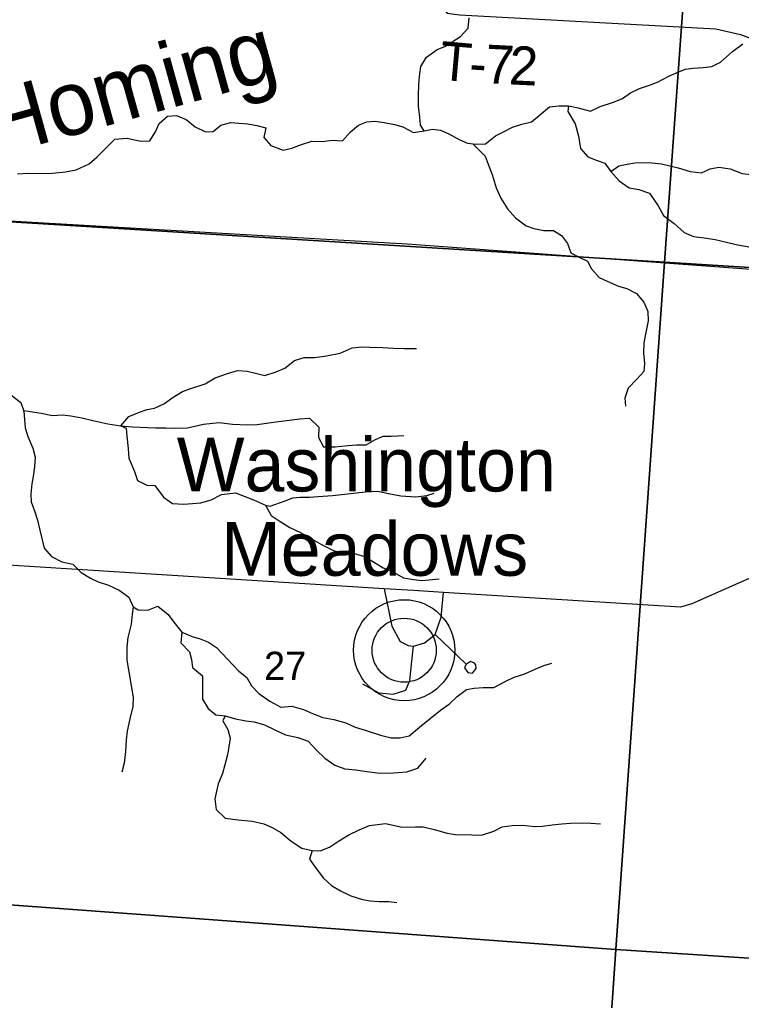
# Model space of a CAD drawing. Extents: x 0 to 42.5, y 0 to 22.
# Drawn here: x 4.014 to 4.545, y 19.377 to 20.099 of the extents above; entities that cross this region are included whole.
import ezdxf

# ---------------------------------------------------------------- set-up
doc = ezdxf.new("R2010")
doc.units = 0
for name, color, linetype in [('GM_X_County_Road', 7, 'Continuous'), ('GM_X_Minor_River', 7, 'Continuous'), ('GM_X_Minor_River_Text', 7, 'Continuous'), ('GM_X_Rail_Line', 7, 'Continuous'), ('GM_X_Section', 7, 'Continuous'), ('GM_X_Section_Text', 7, 'Continuous'), ('GM_X_Township_Road', 7, 'Continuous'), ('GM_X_Township_Road_Text', 7, 'Continuous'), ('GM_X_Unincorporated', 7, 'Continuous'), ('GM_X_Unincorporated_Location', 7, 'Continuous'), ('GM_X_Unincorporated_Text', 7, 'Continuous')]:
    doc.layers.add(name, color=color, linetype=linetype)

msp = doc.modelspace()

# ---------------------------------------------------------------- linework, layer by layer
at = {"layer": 'GM_X_County_Road'}
msp.add_lwpolyline([(4.55979, 19.69172), (4.5089, 19.66909), (4.50055, 19.66669), (4.32613, 19.67757), (4.30419, 19.67894), (4.28243, 19.68029), (3.95904, 19.70046)], dxfattribs=at)
at = {"layer": 'GM_X_Minor_River'}
for points in [[(4.31187, 20.01728), (4.30924, 20.02148), (4.30871, 20.02738), (4.30781, 20.03555), (4.30767, 20.04316), (4.30791, 20.05152), (4.30851, 20.05721), (4.3095, 20.06462), (4.31371, 20.07143), (4.32152, 20.07709), (4.32702, 20.07933), (4.33863, 20.08686), (4.34435, 20.0929), (4.34515, 20.1005)], [(4.15668, 20.01695), (4.1624, 20.02147), (4.1698, 20.02352), (4.17567, 20.02291), (4.18211, 20.02249), (4.18892, 20.0213), (4.19535, 20.01955), (4.19398, 20.01234), (4.19925, 20.00641), (4.20814, 20.00313), (4.21459, 20.0046), (4.22181, 20.00722), (4.22921, 20.00964), (4.23679, 20.00959), (4.24456, 20.01049), (4.25176, 20.01007), (4.25767, 20.01649), (4.26358, 20.02158), (4.26966, 20.02383), (4.27553, 20.02436), (4.28254, 20.02336), (4.29011, 20.02198), (4.29616, 20.02024), (4.30409, 20.01619), (4.31187, 20.01728), (4.31813, 20.01857), (4.324, 20.01778), (4.33005, 20.01508), (4.3376, 20.01085), (4.34384, 20.00834), (4.35008, 20.00754), (4.3571, 20.00768), (4.36433, 20.01353), (4.37079, 20.01691), (4.37687, 20.01991), (4.3839, 20.02214), (4.39092, 20.024), (4.39663, 20.02852), (4.40425, 20.03494), (4.41108, 20.03584), (4.41809, 20.03561), (4.42528, 20.03423), (4.43417, 20.03189), (4.44139, 20.03527), (4.45126, 20.03844), (4.45791, 20.04105), (4.46381, 20.0452), (4.47027, 20.04839), (4.47844, 20.05118), (4.48394, 20.05343), (4.49136, 20.05737), (4.49858, 20.06056), (4.50427, 20.06261), (4.50977, 20.06353), (4.51717, 20.06405), (4.52342, 20.06477), (4.52989, 20.06777), (4.53884, 20.07569), (4.54645, 20.08134)], [(4.41809, 20.03561), (4.41768, 20.03143), (4.42312, 20.02246), (4.42553, 20.01332), (4.42699, 20.00438), (4.43226, 19.99827), (4.43907, 19.99556), (4.44474, 19.99363), (4.44925, 19.98733), (4.45546, 19.98044), (4.46282, 19.97546), (4.46982, 19.97408), (4.47776, 19.97156), (4.48415, 19.96202), (4.48808, 19.95496), (4.49582, 19.94921), (4.50317, 19.94251), (4.51016, 19.93961), (4.51792, 19.93861), (4.52587, 19.93742), (4.53439, 19.93528), (4.54139, 19.93371), (4.55066, 19.93194)], [(4.01287, 19.98556), (4.02083, 19.98608), (4.0358, 19.98599), (4.04812, 19.98724), (4.0559, 19.98852), (4.0654, 19.99302), (4.0715, 19.99811), (4.07722, 20.00416), (4.08446, 20.01114), (4.09337, 20.01203), (4.10321, 20.00969), (4.11003, 20.00984), (4.11443, 20.01665), (4.11712, 20.02271), (4.12303, 20.028), (4.12985, 20.02852), (4.13684, 20.02563), (4.14344, 20.02026), (4.15119, 20.0166), (4.15668, 20.01695)], [(4.34764, 20.00785), (4.35685, 19.99875), (4.35965, 19.99094), (4.36189, 19.98523), (4.36486, 19.97532), (4.36822, 19.9677), (4.37329, 19.95988), (4.37912, 19.95319), (4.38705, 19.94744), (4.39272, 19.9455), (4.39991, 19.94393), (4.40711, 19.94408), (4.41296, 19.94024), (4.41728, 19.93432), (4.41989, 19.92746), (4.42632, 19.924), (4.43198, 19.92149), (4.43498, 19.91577), (4.44063, 19.90927), (4.44648, 19.90657), (4.45499, 19.9031), (4.46104, 19.90116), (4.46803, 19.89769), (4.47348, 19.8912), (4.47648, 19.88434), (4.47681, 19.87749), (4.47487, 19.86895), (4.47349, 19.86136), (4.47326, 19.85376), (4.47397, 19.84615), (4.47355, 19.84027), (4.4684, 19.8346), (4.46192, 19.8278), (4.4596, 19.82059), (4.45995, 19.8147)], [(4.44925, 19.98733), (4.45515, 19.99166), (4.46122, 19.99276), (4.46691, 19.99367), (4.47259, 19.99402), (4.47941, 19.99378), (4.48642, 19.99298), (4.49872, 19.99005), (4.50761, 19.98733), (4.51594, 19.98633), (4.5224, 19.98933), (4.52866, 19.99062), (4.53699, 19.98923), (4.54587, 19.98595), (4.55742, 19.98473), (4.56387, 19.98583), (4.57071, 19.98902), (4.58059, 19.99295), (4.59687, 20.00566)], [(4.08886, 19.80016), (4.09478, 19.80697), (4.10257, 19.81034), (4.10807, 19.8122), (4.11357, 19.81312), (4.12098, 19.81668), (4.1265, 19.82083), (4.13411, 19.82553), (4.14038, 19.82758), (4.15082, 19.83112), (4.15823, 19.83545), (4.16716, 19.83862), (4.17475, 19.84085), (4.18176, 19.84043), (4.18782, 19.83906), (4.19463, 19.8373), (4.20222, 19.83973), (4.20944, 19.84253), (4.21667, 19.84837), (4.2237, 19.85042), (4.23128, 19.85056), (4.24019, 19.85165), (4.25005, 19.85367), (4.25898, 19.85761), (4.26619, 19.85832), (4.27206, 19.85809), (4.28153, 19.85784), (4.2893, 19.85741), (4.29725, 19.85717), (4.30635, 19.85711)], [(4.0079, 19.82311), (4.01526, 19.81736), (4.0175, 19.81107), (4.01802, 19.80461), (4.01837, 19.79872), (4.02041, 19.79243), (4.02396, 19.78386), (4.02581, 19.777), (4.0252, 19.76998), (4.02421, 19.76295), (4.02323, 19.75744), (4.02262, 19.75004), (4.02277, 19.74433), (4.02557, 19.73691), (4.02743, 19.73062), (4.02928, 19.72339), (4.03094, 19.71635), (4.03242, 19.71025), (4.03788, 19.70395), (4.04543, 19.7001), (4.05357, 19.69834), (4.05959, 19.69222), (4.06658, 19.68799), (4.07225, 19.68529), (4.07981, 19.68296), (4.08756, 19.67911), (4.09473, 19.67413), (4.09791, 19.66707), (4.09712, 19.66157), (4.09631, 19.65416), (4.09398, 19.64448), (4.09318, 19.63727), (4.09331, 19.62776), (4.0944, 19.62054), (4.09531, 19.61483), (4.0966, 19.60741), (4.09788, 19.60056), (4.09765, 19.59353), (4.09532, 19.58461), (4.09356, 19.5755), (4.09276, 19.56904), (4.09233, 19.5605), (4.09133, 19.55176), (4.08959, 19.54531)], [(4.0175, 19.81107), (4.0175, 19.81145), (4.03018, 19.80947), (4.03851, 19.80771), (4.0459, 19.80823), (4.05196, 19.80762), (4.0601, 19.80605), (4.06823, 19.8041), (4.07921, 19.80175), (4.08886, 19.80016), (4.09738, 19.79935), (4.10837, 19.7989), (4.11424, 19.79867), (4.12182, 19.79862), (4.12826, 19.79839), (4.13774, 19.79871), (4.14969, 19.80148), (4.16107, 19.80255), (4.17091, 19.80135), (4.1819, 19.8009), (4.1891, 19.80123), (4.20105, 19.80287), (4.21451, 19.80468), (4.22058, 19.80521), (4.22759, 19.80592), (4.23437, 19.79923), (4.23414, 19.79163), (4.23789, 19.78476), (4.24641, 19.78471), (4.2557, 19.7856), (4.26215, 19.78613), (4.26916, 19.78627), (4.27619, 19.79003), (4.28189, 19.79265), (4.28758, 19.79262), (4.29705, 19.79313)], [(4.08886, 19.80016), (4.09264, 19.79843), (4.09317, 19.79253), (4.09426, 19.7836), (4.09459, 19.77637), (4.09889, 19.76646), (4.10112, 19.75999), (4.10792, 19.75652), (4.1138, 19.75629), (4.12019, 19.7477), (4.12679, 19.74291), (4.13512, 19.74247), (4.14157, 19.743), (4.14764, 19.74353), (4.15523, 19.74577), (4.16283, 19.74971), (4.17326, 19.75097), (4.1795, 19.74846), (4.18649, 19.74575), (4.19518, 19.7419), (4.1995, 19.73427), (4.20534, 19.73024), (4.21308, 19.72525), (4.22102, 19.72159), (4.2365, 19.71275), (4.24519, 19.70832), (4.25144, 19.70695), (4.26147, 19.70593), (4.26809, 19.70399), (4.2747, 19.70015), (4.28168, 19.69573), (4.28773, 19.69341), (4.2968, 19.68822), (4.30399, 19.68704), (4.30986, 19.68624), (4.31555, 19.68677), (4.32294, 19.68749)], [(4.19518, 19.7419), (4.19859, 19.74112), (4.20979, 19.74504), (4.2153, 19.74709), (4.2208, 19.74763), (4.22762, 19.74758), (4.23406, 19.74811), (4.24449, 19.74899), (4.25776, 19.75043), (4.26857, 19.75169), (4.27786, 19.7522), (4.28562, 19.75044), (4.2947, 19.74867), (4.30587, 19.74784), (4.31384, 19.74893), (4.31934, 19.7506)], [(4.09791, 19.66707), (4.10168, 19.66477), (4.10869, 19.66453), (4.11591, 19.66753), (4.12364, 19.6614), (4.12777, 19.65567), (4.13379, 19.64822), (4.14135, 19.64513), (4.14722, 19.64338), (4.15326, 19.64087), (4.15911, 19.63703), (4.16721, 19.62843), (4.17549, 19.61964), (4.18153, 19.61504), (4.1849, 19.60874), (4.19036, 19.6032), (4.19829, 19.59744), (4.20641, 19.59302), (4.21456, 19.59373), (4.22326, 19.59139), (4.22987, 19.58831), (4.23743, 19.58541), (4.24538, 19.58403), (4.25427, 19.5815), (4.26127, 19.57841), (4.26845, 19.57609), (4.2798, 19.57259), (4.28756, 19.57045), (4.29438, 19.57041), (4.30083, 19.57208), (4.30845, 19.5783), (4.31625, 19.58471), (4.32387, 19.59094), (4.33053, 19.59564), (4.33625, 19.60093), (4.3431, 19.60602), (4.34879, 19.60712), (4.35542, 19.60746), (4.36319, 19.6076), (4.37194, 19.61229), (4.37802, 19.6151), (4.38599, 19.61752), (4.39359, 19.62109), (4.39986, 19.62371), (4.40575, 19.62557)], [(4.13379, 19.64822), (4.13299, 19.64043), (4.1392, 19.63393), (4.14068, 19.62822), (4.14159, 19.62232), (4.14876, 19.6162), (4.1489, 19.60802), (4.14884, 19.5989), (4.15297, 19.59222), (4.15881, 19.58743), (4.16563, 19.58663), (4.1732, 19.58449), (4.18077, 19.58292), (4.18701, 19.58231), (4.19458, 19.58017), (4.20214, 19.57651), (4.20988, 19.57285), (4.21897, 19.5707), (4.22653, 19.56819), (4.23255, 19.56169), (4.23896, 19.55556), (4.24613, 19.55039), (4.25369, 19.54768), (4.26145, 19.54687), (4.26978, 19.54567), (4.27736, 19.54467), (4.28607, 19.54443), (4.29252, 19.54496), (4.29915, 19.54548), (4.30732, 19.54809), (4.31342, 19.55566)], [(4.16563, 19.58663), (4.1639, 19.58303), (4.16746, 19.57674), (4.16913, 19.57026), (4.16833, 19.56381), (4.16716, 19.55792), (4.16541, 19.55071), (4.16348, 19.54426), (4.1604, 19.53668), (4.15806, 19.52567), (4.15896, 19.51769), (4.16555, 19.51137), (4.17502, 19.51017), (4.18543, 19.50915), (4.19395, 19.5072), (4.20018, 19.5045), (4.20642, 19.50085), (4.21415, 19.49453), (4.22188, 19.48935), (4.22945, 19.48759), (4.23551, 19.48736), (4.24235, 19.48998), (4.24901, 19.49449), (4.25643, 19.49901), (4.26403, 19.50276), (4.27182, 19.50594), (4.28357, 19.50757), (4.29587, 19.50465), (4.30554, 19.50496), (4.31122, 19.50493), (4.31917, 19.50317), (4.32882, 19.50044), (4.33487, 19.49945), (4.347, 19.49919), (4.3542, 19.49876), (4.36312, 19.50174), (4.3692, 19.50493), (4.3766, 19.50603), (4.38418, 19.50617), (4.39346, 19.50535), (4.39895, 19.5055), (4.40597, 19.5066), (4.41318, 19.50731), (4.41962, 19.50765), (4.42853, 19.50798), (4.43459, 19.50775), (4.4416, 19.50732)], [(4.22945, 19.48759), (4.22771, 19.48133), (4.23165, 19.47522), (4.23786, 19.4672), (4.24388, 19.46184), (4.25049, 19.4578), (4.25805, 19.45415), (4.26656, 19.45143), (4.27224, 19.45063), (4.27887, 19.45002), (4.28588, 19.44998), (4.29194, 19.44937)]]:
    msp.add_lwpolyline(points, dxfattribs=at)
at = {"layer": 'GM_X_Rail_Line'}
msp.add_lwpolyline([(2.61877, 19.97568), (2.65326, 19.99211), (2.69136, 20.00655), (2.71989, 20.01446), (2.74816, 20.0195), (2.77247, 20.02118), (2.80231, 20.02106), (2.83481, 20.01941), (2.91733, 20.01403), (3.26401, 19.99461), (3.61724, 19.97619), (3.94708, 19.95463), (4.29937, 19.93411), (4.5956, 19.91226), (5.05555, 19.8842), (5.17532, 19.87894), (5.25442, 19.87492), (5.30129, 19.87455), (5.33367, 19.88019), (5.36925, 19.89196), (5.40278, 19.90809), (5.43829, 19.93181), (5.47396, 19.96523), (5.54064, 20.03224)], dxfattribs=at)
at = {"layer": 'GM_X_Section'}
for points in [[(4.01124, 20.45591), (4.52494, 20.42409), (4.48862, 19.92064), (3.97586, 19.95227)], [(5.05423, 20.39046), (5.01142, 19.88812), (4.48862, 19.92064), (4.52494, 20.42409)], [(3.97586, 19.95227), (4.48862, 19.92064), (4.45285, 19.41472), (3.94032, 19.4526)], [(4.48862, 19.92064), (5.01142, 19.88812), (4.96593, 19.38143), (4.45285, 19.41472)], [(3.94032, 19.4526), (4.45285, 19.41472), (4.41842, 18.91278), (4.41142, 18.91319), (3.90077, 18.94861)], [(4.45285, 19.41472), (4.96593, 19.38143), (4.92537, 18.8751), (4.41842, 18.91278)]]:
    msp.add_lwpolyline(points, close=True, dxfattribs=at)
at = {"layer": 'GM_X_Township_Road'}
for points in [[(4.25615, 20.1882), (4.296, 20.14191), (4.32531, 20.10786), (4.32888, 20.10404), (4.33796, 20.10264), (4.52648, 20.09239), (4.54463, 20.08826), (4.55577, 20.08418), (4.5961, 20.05672), (4.6248, 20.04265), (4.63589, 20.03529), (4.63998, 20.02916), (4.64842, 20.00815), (4.65349, 20.0041), (4.66608, 19.99615), (4.68652, 19.97994)], [(4.28243, 19.68029), (4.2881, 19.65277), (4.29419, 19.64147), (4.30021, 19.63853), (4.30419, 19.6379), (4.31219, 19.64044), (4.3201, 19.64657), (4.3244, 19.65924), (4.32613, 19.67757)], [(4.3201, 19.64657), (4.34295, 19.62468), (4.34168, 19.62195), (4.34409, 19.61868), (4.34749, 19.61806), (4.3502, 19.62158), (4.35004, 19.6243), (4.34886, 19.62559), (4.34598, 19.62662), (4.34304, 19.62478)], [(4.26663, 19.61018), (4.27867, 19.60373), (4.28908, 19.60262), (4.29841, 19.60551), (4.30135, 19.61269), (4.30289, 19.62691), (4.30419, 19.6379)]]:
    msp.add_lwpolyline(points, dxfattribs=at)
at = {"layer": 'GM_X_Unincorporated'}
for radius in [0.0372, 0.02358]:
    msp.add_circle((4.29725, 19.63502), radius, dxfattribs=at)
at = {"layer": 'GM_X_Unincorporated_Location'}
msp.add_line((4.29725, 19.63502), (4.29725, 19.63502), dxfattribs=at)

# ---------------------------------------------------------------- texts
at = {"layer": 'GM_X_Minor_River_Text'}
msp.add_text('Homing', height=0.047347, rotation=15.53186, dxfattribs=at).set_placement((3.99651, 19.99809))
at = {"layer": 'GM_X_Section_Text'}
msp.add_text('27', height=0.020928, rotation=0.00001, dxfattribs=at).set_placement((4.19412, 19.61298))
at = {"layer": 'GM_X_Township_Road_Text'}
for s, rotation, p in [('T', 354.96232, (4.3224, 20.0551)), ('7', 357.05623, (4.35634, 20.05249)), ('2', 357.14424, (4.37386, 20.05159)), ('-', 356.74586, (4.34453, 20.05316))]:
    msp.add_text(s, height=0.02841, rotation=rotation, dxfattribs=at).set_placement(p)
at = {"layer": 'GM_X_Unincorporated_Text'}
for s, p in [('Washington', (4.12995, 19.75189)), ('Meadows', (4.16245, 19.68981))]:
    msp.add_text(s, height=0.039489, rotation=0.00001, dxfattribs=at).set_placement(p)

doc.saveas('drawing.dxf')
